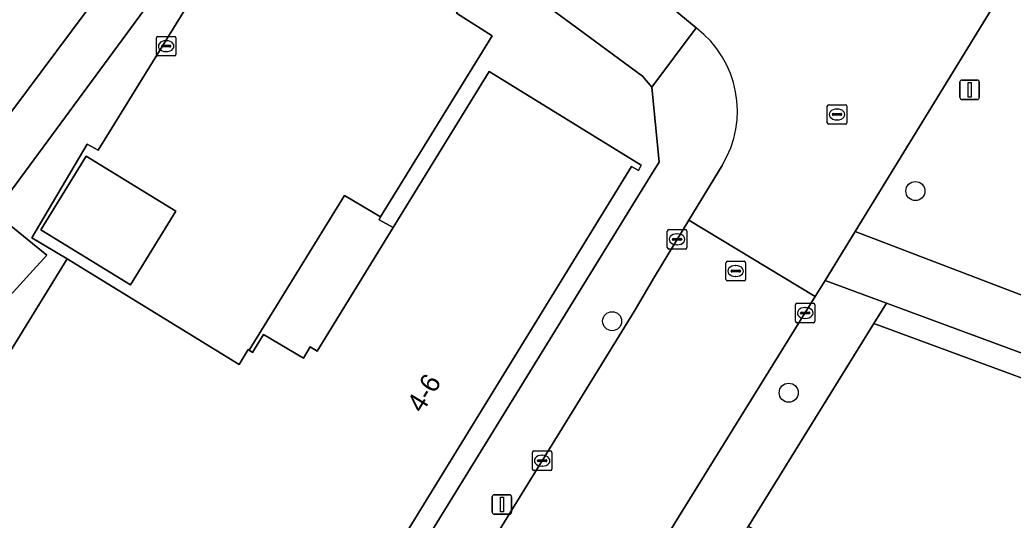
# Model space of a CAD drawing. Extents: x 162803 to 163818, y 381639 to 382475.
# Drawn here: x 163036.2 to 163087.2, y 381869.7 to 381895.4 of the extents above; entities that cross this region are included whole.
import ezdxf

# ---------------------------------------------------------------- set-up
doc = ezdxf.new("R2010")
doc.units = 0
for name, color, linetype in [('IMGEO_Boom', 7, 'Continuous'), ('IMGEO_Erf', 7, 'Continuous'), ('IMGEO_Groenvoorziening', 7, 'Continuous'), ('IMGEO_Hek', 7, 'Continuous'), ('IMGEO_Kolk', 7, 'Continuous'), ('IMGEO_Lichtmast', 7, 'Continuous'), ('IMGEO_Open_loods', 7, 'Continuous'), ('IMGEO_Pand', 7, 'Continuous'), ('IMGEO_Pand_nummerreeks', 7, 'Continuous'), ('IMGEO_Parkeervlak_open', 7, 'Continuous'), ('IMGEO_Rijbaan_lokaal_open', 7, 'Continuous'), ('IMGEO_Rioolput', 7, 'Continuous'), ('IMGEO_Voetpad_gesloten', 7, 'Continuous'), ('IMGEO_Voetpad_halfverhard', 7, 'Continuous'), ('IMGEO_Voetpad_open', 7, 'Continuous')]:
    doc.layers.add(name, color=color, linetype=linetype)

msp = doc.modelspace()

# ---------------------------------------------------------------- linework, layer by layer
at = {"layer": 'IMGEO_Boom'}
for centre in [(163082.188, 381886.567), (163066.621, 381879.881), (163075.685, 381876.209)]:
    msp.add_circle(centre, 0.489, dxfattribs=at)
at = {"layer": 'IMGEO_Erf'}
msp.add_lwpolyline([(163038.651, 381883.086), (163036.828, 381884.162), (163039.676, 381888.972), (163040.229, 381888.673), (163050.041, 381904.572), (163054.928, 381901.596), (163055.361, 381902.269), (163050.243, 381906.292), (163034.914, 381885.439), (163037.605, 381883.275), (163019.349, 381863.218), (163031.785, 381852.208), (163033.858, 381855.537), (163033.587, 381855.698), (163033.798, 381856.014), (163025.478, 381861.115), (163025.295, 381860.793), (163025.018, 381860.951)], close=True, dxfattribs=at)
msp.add_lwpolyline([(163023.213, 381895.682), (163025.63, 381893.703), (163027.222, 381895.579), (163029.852, 381893.348), (163030.812, 381894.576), (163035.802, 381890.676), (163039.628, 381895.786)], dxfattribs=at)
at = {"layer": 'IMGEO_Groenvoorziening'}
for points in [[(163114.975, 381943.024), (163089.592, 381901.666), (163087.523, 381898.23), (163086.13, 381895.957), (163079.099, 381884.487), (163082.234, 381883.288), (163093.032, 381879.159), (163093.046, 381879.154), (163099.204, 381891.124), (163115.517, 381885.092), (163117.64, 381890.509), (163137.039, 381941.324)], [(163080.701, 381880.807), (163080.058, 381879.766), (163094.718, 381874.361), (163106.979, 381869.84), (163107.395, 381869.476), (163107.586, 381869.167), (163107.691, 381868.676), (163107.588, 381868.15), (163106.369, 381864.493), (163105.791, 381862.206), (163105.668, 381861.359), (163105.323, 381858.982), (163102.085, 381839.303), (163103.298, 381839.057), (163105.724, 381853.567), (163106.512, 381858.816)], [(163106.871, 381871.137), (163080.701, 381880.807)], [(163102.801, 381836.083), (163103.298, 381839.057), (163102.085, 381839.303), (163105.323, 381858.982), (163105.668, 381861.359), (163103.938, 381861.555), (163101.326, 381862.698), (163100.347, 381864.983), (163100.592, 381866.37), (163099.245, 381865.84), (163096.919, 381865.881), (163094.553, 381867.962), (163093.941, 381870.94), (163094.718, 381874.361), (163080.058, 381879.766), (163073.629, 381869.358), (163092.744, 381857.74), (163097.666, 381854.748), (163098.212, 381854.416), (163076.88, 381813.818)]]:
    msp.add_lwpolyline(points, dxfattribs=at)
for points in [[(163068.653, 381891.896), (163068.177, 381892.47), (163060.268, 381898.298), (163058.635, 381895.702), (163060.471, 381894.547), (163054.736, 381885.241), (163054.657, 381885.087), (163055.376, 381884.686), (163060.306, 381892.706), (163068.12, 381887.891), (163067.971, 381887.615), (163067.621, 381887.819), (163052.073, 381862.544), (163052.426, 381862.343), (163052.243, 381862.047), (163052.762, 381861.77), (163052.897, 381861.856), (163068.715, 381887.535), (163069.028, 381888.05)], [(163080.058, 381879.766), (163080.701, 381880.807), (163077.556, 381881.969), (163077.052, 381881.146), (163070.17, 381870.045), (163067.916, 381866.384), (163066.543, 381864.226), (163069.38, 381862.489), (163071.602, 381866.077), (163073.629, 381869.358)]]:
    msp.add_lwpolyline(points, close=True, dxfattribs=at)
at = {"layer": 'IMGEO_Hek'}
msp.add_lwpolyline([(163050.243, 381906.292), (163034.914, 381885.439), (163037.605, 381883.275), (163019.349, 381863.218)], dxfattribs=at)
at = {"layer": 'IMGEO_Kolk'}
for p, q in [((163043.226, 381893.583), (163043.226, 381894.435)), ((163043.301, 381894.509), (163044.153, 381894.509)), ((163043.714, 381894.289), (163043.739, 381894.289)), ((163044.227, 381894.435), (163044.227, 381893.583)), ((163043.485, 381894.003), (163043.485, 381894.015)), ((163043.923, 381893.966), (163043.525, 381893.966)), ((163043.528, 381894.052), (163043.926, 381894.052)), ((163043.737, 381893.729), (163043.712, 381893.729)), ((163043.969, 381894.015), (163043.969, 381894.003)), ((163044.153, 381893.509), (163043.301, 381893.509)), ((163069.454, 381883.66), (163069.454, 381884.512)), ((163069.529, 381884.586), (163070.381, 381884.586)), ((163070.455, 381884.512), (163070.455, 381883.66)), ((163069.713, 381884.08), (163069.713, 381884.092)), ((163070.151, 381884.043), (163069.753, 381884.043)), ((163069.756, 381884.129), (163070.154, 381884.129)), ((163069.942, 381884.366), (163069.967, 381884.366)), ((163070.197, 381884.092), (163070.197, 381884.08)), ((163070.381, 381883.586), (163069.529, 381883.586)), ((163069.965, 381883.806), (163069.94, 381883.806)), ((163076.032, 381879.876), (163076.032, 381880.728)), ((163076.107, 381880.802), (163076.959, 381880.802)), ((163076.52, 381880.582), (163076.545, 381880.582)), ((163077.033, 381880.728), (163077.033, 381879.876)), ((163076.291, 381880.296), (163076.291, 381880.308)), ((163076.729, 381880.259), (163076.331, 381880.259)), ((163076.334, 381880.345), (163076.732, 381880.345)), ((163076.543, 381880.022), (163076.518, 381880.022)), ((163076.775, 381880.308), (163076.775, 381880.296)), ((163076.959, 381879.802), (163076.107, 381879.802)), ((163062.604, 381873.215), (163063.456, 381873.215)), ((163062.529, 381872.289), (163062.529, 381873.141)), ((163062.788, 381872.709), (163062.788, 381872.721)), ((163062.831, 381872.758), (163063.229, 381872.758)), ((163063.017, 381872.995), (163063.042, 381872.995)), ((163063.272, 381872.721), (163063.272, 381872.709)), ((163063.53, 381873.141), (163063.53, 381872.289)), ((163063.456, 381872.215), (163062.604, 381872.215)), ((163063.226, 381872.672), (163062.828, 381872.672)), ((163063.04, 381872.435), (163063.015, 381872.435))]:
    msp.add_line(p, q, dxfattribs=at)
for points in [[(163043.226, 381893.583), (163043.226, 381894.435)], [(163043.301, 381894.509), (163044.153, 381894.509)], [(163044.227, 381894.435), (163044.227, 381893.583)], [(163044.153, 381893.509), (163043.301, 381893.509)], [(163069.454, 381883.66), (163069.454, 381884.512)], [(163069.529, 381884.586), (163070.381, 381884.586)], [(163070.455, 381884.512), (163070.455, 381883.66)], [(163070.381, 381883.586), (163069.529, 381883.586)], [(163076.032, 381879.876), (163076.032, 381880.728)], [(163076.107, 381880.802), (163076.959, 381880.802)], [(163077.033, 381880.728), (163077.033, 381879.876)], [(163076.959, 381879.802), (163076.107, 381879.802)], [(163062.604, 381873.215), (163063.456, 381873.215)], [(163062.529, 381872.289), (163062.529, 381873.141)], [(163063.53, 381873.141), (163063.53, 381872.289)], [(163063.456, 381872.215), (163062.604, 381872.215)]]:
    msp.add_lwpolyline(points, dxfattribs=at)
for centre, radius, start, end in [((163043.303, 381894.433), 0.0765, 91.552, 178.448), ((163043.303, 381894.433), 0.0765, 91.552, 178.448), ((163044.151, 381894.433), 0.0765, 1.552, 88.448), ((163044.151, 381894.433), 0.0765, 1.552, 88.448), ((163043.525, 381894.012), 0.0403, 85.8775, 175.7526), ((163043.522, 381894.002), 0.0366, 178.938, 274.7102), ((163043.926, 381894.009), 0.043, 264.8664, 352.4533), ((163043.93, 381894.014), 0.0386, 1.7309, 96.639), ((163043.303, 381893.585), 0.0765, 181.552, 268.448), ((163043.303, 381893.585), 0.0765, 181.552, 268.448), ((163044.151, 381893.585), 0.0765, 271.552, 358.448), ((163044.151, 381893.585), 0.0765, 271.552, 358.448), ((163069.531, 381884.51), 0.0765, 91.552, 178.448), ((163069.531, 381884.51), 0.0765, 91.552, 178.448), ((163070.379, 381884.51), 0.0765, 1.552, 88.448), ((163070.379, 381884.51), 0.0765, 1.552, 88.448), ((163069.753, 381884.089), 0.0403, 85.8775, 175.7526), ((163069.75, 381884.079), 0.0366, 178.938, 274.7102), ((163070.154, 381884.086), 0.043, 264.8664, 352.4533), ((163070.158, 381884.091), 0.0386, 1.7309, 96.639), ((163069.531, 381883.662), 0.0765, 181.552, 268.448), ((163069.531, 381883.662), 0.0765, 181.552, 268.448), ((163070.379, 381883.662), 0.0765, 271.552, 358.448), ((163070.379, 381883.662), 0.0765, 271.552, 358.448), ((163076.109, 381880.726), 0.0765, 91.552, 178.448), ((163076.109, 381880.726), 0.0765, 91.552, 178.448), ((163076.957, 381880.726), 0.0765, 1.552, 88.448), ((163076.957, 381880.726), 0.0765, 1.552, 88.448), ((163076.109, 381879.878), 0.0765, 181.552, 268.448), ((163076.109, 381879.878), 0.0765, 181.552, 268.448), ((163076.331, 381880.305), 0.0403, 85.8775, 175.7526), ((163076.328, 381880.295), 0.0366, 178.938, 274.7102), ((163076.732, 381880.302), 0.043, 264.8664, 352.4533), ((163076.736, 381880.307), 0.0386, 1.7309, 96.639), ((163076.957, 381879.878), 0.0765, 271.552, 358.448), ((163076.957, 381879.878), 0.0765, 271.552, 358.448), ((163062.606, 381873.139), 0.0765, 91.552, 178.448), ((163062.606, 381873.139), 0.0765, 91.552, 178.448), ((163063.454, 381873.139), 0.0765, 1.552, 88.448), ((163063.454, 381873.139), 0.0765, 1.552, 88.448), ((163062.828, 381872.718), 0.0403, 85.8775, 175.7526), ((163062.825, 381872.708), 0.0366, 178.938, 274.7102), ((163063.229, 381872.715), 0.043, 264.8664, 352.4533), ((163063.233, 381872.72), 0.0386, 1.7309, 96.639), ((163062.606, 381872.291), 0.0765, 181.552, 268.448), ((163062.606, 381872.291), 0.0765, 181.552, 268.448), ((163063.454, 381872.291), 0.0765, 271.552, 358.448), ((163063.454, 381872.291), 0.0765, 271.552, 358.448)]:
    msp.add_arc(centre, radius, start, end, dxfattribs=at)
for centre, major_axis, ratio, start_param, end_param in [((163043.713, 381894.009), (-0.387, 0.002), 0.722429, 4.712389, 7.853982), ((163043.738, 381894.009), (-0.39, 0.002), 0.717154, 1.570796, 4.712389), ((163069.941, 381884.086), (-0.387, 0.002), 0.722429, 4.712389, 7.853982), ((163069.966, 381884.086), (-0.39, 0.002), 0.717154, 1.570796, 4.712389), ((163076.519, 381880.302), (-0.387, 0.002), 0.722429, 4.712389, 7.853982), ((163076.544, 381880.302), (-0.39, 0.002), 0.717154, 1.570796, 4.712389), ((163063.016, 381872.715), (-0.387, 0.002), 0.722429, 4.712389, 7.853982), ((163063.041, 381872.715), (-0.39, 0.002), 0.717154, 1.570796, 4.712389)]:
    msp.add_ellipse(centre, major_axis=major_axis, ratio=ratio, start_param=start_param, end_param=end_param, dxfattribs=at)
at = {"layer": 'IMGEO_Lichtmast'}
for p, q in [((163084.476, 381891.369), (163084.476, 381892.169)), ((163084.476, 381892.169), (163084.476, 381891.369)), ((163084.576, 381892.269), (163085.366, 381892.269)), ((163085.366, 381892.269), (163084.576, 381892.269)), ((163085.466, 381892.169), (163085.466, 381891.369)), ((163085.466, 381891.369), (163085.466, 381892.169)), ((163085.366, 381891.269), (163084.576, 381891.269)), ((163084.576, 381891.269), (163085.366, 381891.269)), ((163060.467, 381870.066), (163060.467, 381870.866)), ((163060.467, 381870.866), (163060.467, 381870.066)), ((163060.567, 381870.966), (163061.357, 381870.966)), ((163061.357, 381870.966), (163060.567, 381870.966)), ((163061.457, 381870.866), (163061.457, 381870.066)), ((163061.457, 381870.066), (163061.457, 381870.866)), ((163061.357, 381869.966), (163060.567, 381869.966)), ((163060.567, 381869.966), (163061.357, 381869.966))]:
    msp.add_line(p, q, dxfattribs=at)
for points in [[(163084.896, 381892.144), (163085.046, 381892.144), (163085.046, 381891.394), (163084.896, 381891.394), (163084.896, 381892.144)], [(163060.887, 381870.841), (163061.037, 381870.841), (163061.037, 381870.091), (163060.887, 381870.091), (163060.887, 381870.841)]]:
    msp.add_lwpolyline(points, dxfattribs=at)
for centre, start, end in [((163084.576, 381892.169), 90, 180), ((163084.576, 381892.169), 90, 180), ((163085.366, 381892.169), 0, 90), ((163085.366, 381892.169), 360, 90), ((163084.576, 381891.369), 180, 270), ((163084.576, 381891.369), 180, 270), ((163085.366, 381891.369), 270, 0), ((163085.366, 381891.369), 270, 0), ((163060.567, 381870.866), 90, 180), ((163060.567, 381870.866), 90, 180), ((163061.357, 381870.866), 0, 90), ((163061.357, 381870.866), 360, 90), ((163060.567, 381870.066), 180, 270), ((163060.567, 381870.066), 180, 270), ((163061.357, 381870.066), 270, 0), ((163061.357, 381870.066), 270, 0)]:
    msp.add_arc(centre, 0.1, start, end, dxfattribs=at)
at = {"layer": 'IMGEO_Open_loods'}
msp.add_lwpolyline([(163044.218, 381885.539), (163039.624, 381888.364), (163037.291, 381884.581), (163041.895, 381881.752)], close=True, dxfattribs=at)
at = {"layer": 'IMGEO_Pand'}
msp.add_lwpolyline([(163052.073, 381862.544), (163067.621, 381887.819), (163067.971, 381887.615), (163068.12, 381887.891), (163060.306, 381892.706), (163055.376, 381884.686), (163051.48, 381878.348), (163051.127, 381878.561), (163050.773, 381877.977), (163048.727, 381879.199), (163048.162, 381878.277), (163047.993, 381878.397), (163047.942, 381878.433), (163047.476, 381877.66), (163038.651, 381883.086), (163025.018, 381860.951)], dxfattribs=at)
at = {"layer": 'IMGEO_Parkeervlak_open'}
for points in [[(163054.928, 381901.596), (163050.041, 381904.572), (163040.229, 381888.673), (163039.676, 381888.972), (163036.828, 381884.162), (163038.651, 381883.086), (163047.476, 381877.66), (163047.942, 381878.433), (163047.993, 381878.397), (163052.886, 381886.336), (163054.736, 381885.241), (163060.471, 381894.547), (163058.635, 381895.702), (163060.268, 381898.298)], [(163041.895, 381881.752), (163037.291, 381884.581), (163039.624, 381888.364), (163044.218, 381885.539)]]:
    msp.add_lwpolyline(points, close=True, dxfattribs=at)
at = {"layer": 'IMGEO_Rijbaan_lokaal_open'}
for points in [[(163072.265, 381887.886), (163070.551, 381885.066), (163077.052, 381881.146), (163077.556, 381881.969), (163079.099, 381884.487), (163086.13, 381895.957), (163087.523, 381898.23), (163081.136, 381902.235), (163079.504, 381899.647)], [(163072.605, 381898.25), (163071.739, 381898.909), (163069.543, 381896.09), (163070.942, 381894.943)]]:
    msp.add_lwpolyline(points, dxfattribs=at)
msp.add_lwpolyline([(163066.543, 381864.226), (163067.916, 381866.384), (163070.17, 381870.045), (163077.052, 381881.146), (163070.551, 381885.066), (163068.789, 381882.168), (163067.744, 381880.386), (163057.663, 381863.991), (163055.048, 381859.753), (163051.115, 381853.378), (163048.348, 381848.843), (163045.94, 381844.899), (163052.231, 381840.99), (163057.473, 381849.543), (163062.554, 381857.831), (163064.731, 381861.322)], close=True, dxfattribs=at)
msp.add_arc((163067.7, 381890.683), 5.353, 328.5049, 52.7314, dxfattribs=at)
at = {"layer": 'IMGEO_Rioolput'}
for p, q in [((163077.666, 381890.074), (163077.666, 381890.926)), ((163077.741, 381891), (163078.593, 381891)), ((163078.154, 381890.78), (163078.179, 381890.78)), ((163078.667, 381890.926), (163078.667, 381890.074)), ((163077.925, 381890.494), (163077.925, 381890.506)), ((163078.363, 381890.457), (163077.965, 381890.457)), ((163077.968, 381890.543), (163078.366, 381890.543)), ((163078.177, 381890.22), (163078.152, 381890.22)), ((163078.409, 381890.506), (163078.409, 381890.494)), ((163078.593, 381890), (163077.741, 381890)), ((163072.541, 381882.957), (163073.393, 381882.957)), ((163072.466, 381882.031), (163072.466, 381882.883)), ((163072.725, 381882.451), (163072.725, 381882.463)), ((163073.163, 381882.414), (163072.765, 381882.414)), ((163072.768, 381882.5), (163073.166, 381882.5)), ((163072.954, 381882.737), (163072.979, 381882.737)), ((163073.209, 381882.463), (163073.209, 381882.451)), ((163073.467, 381882.883), (163073.467, 381882.031)), ((163073.393, 381881.957), (163072.541, 381881.957)), ((163072.977, 381882.177), (163072.952, 381882.177))]:
    msp.add_line(p, q, dxfattribs=at)
for points in [[(163077.666, 381890.074), (163077.666, 381890.926)], [(163077.741, 381891), (163078.593, 381891)], [(163078.667, 381890.926), (163078.667, 381890.074)], [(163078.593, 381890), (163077.741, 381890)], [(163072.541, 381882.957), (163073.393, 381882.957)], [(163072.466, 381882.031), (163072.466, 381882.883)], [(163073.467, 381882.883), (163073.467, 381882.031)], [(163073.393, 381881.957), (163072.541, 381881.957)]]:
    msp.add_lwpolyline(points, dxfattribs=at)
for centre, radius, start, end in [((163077.743, 381890.924), 0.0765, 91.552, 178.448), ((163077.743, 381890.924), 0.0765, 91.552, 178.448), ((163078.591, 381890.924), 0.0765, 1.552, 88.448), ((163078.591, 381890.924), 0.0765, 1.552, 88.448), ((163077.743, 381890.076), 0.0765, 181.552, 268.448), ((163077.743, 381890.076), 0.0765, 181.552, 268.448), ((163077.965, 381890.503), 0.0403, 85.8775, 175.7526), ((163077.962, 381890.493), 0.0366, 178.938, 274.7102), ((163078.366, 381890.5), 0.043, 264.8664, 352.4533), ((163078.37, 381890.505), 0.0386, 1.7309, 96.639), ((163078.591, 381890.076), 0.0765, 271.552, 358.448), ((163078.591, 381890.076), 0.0765, 271.552, 358.448), ((163072.543, 381882.881), 0.0765, 91.552, 178.448), ((163072.543, 381882.881), 0.0765, 91.552, 178.448), ((163073.391, 381882.881), 0.0765, 1.552, 88.448), ((163073.391, 381882.881), 0.0765, 1.552, 88.448), ((163072.765, 381882.46), 0.0403, 85.8775, 175.7526), ((163072.762, 381882.45), 0.0366, 178.938, 274.7102), ((163073.166, 381882.457), 0.043, 264.8664, 352.4533), ((163073.17, 381882.462), 0.0386, 1.7309, 96.639), ((163072.543, 381882.033), 0.0765, 181.552, 268.448), ((163072.543, 381882.033), 0.0765, 181.552, 268.448), ((163073.391, 381882.033), 0.0765, 271.552, 358.448), ((163073.391, 381882.033), 0.0765, 271.552, 358.448)]:
    msp.add_arc(centre, radius, start, end, dxfattribs=at)
for centre, major_axis, ratio, start_param, end_param in [((163078.153, 381890.5), (-0.387, 0.002), 0.722429, 4.712389, 7.853982), ((163078.178, 381890.5), (-0.39, 0.002), 0.717154, 1.570796, 4.712389), ((163072.953, 381882.457), (-0.387, 0.002), 0.722429, 4.712389, 7.853982), ((163072.978, 381882.457), (-0.39, 0.002), 0.717154, 1.570796, 4.712389)]:
    msp.add_ellipse(centre, major_axis=major_axis, ratio=ratio, start_param=start_param, end_param=end_param, dxfattribs=at)
at = {"layer": 'IMGEO_Voetpad_gesloten'}
msp.add_lwpolyline([(163054.657, 381885.087), (163054.736, 381885.241), (163052.886, 381886.336), (163047.993, 381878.397), (163048.162, 381878.277), (163048.727, 381879.199), (163050.773, 381877.977), (163051.127, 381878.561), (163051.48, 381878.348), (163055.376, 381884.686)], close=True, dxfattribs=at)
msp.add_lwpolyline([(163108.123, 381873.628), (163093.046, 381879.154), (163093.032, 381879.159), (163082.234, 381883.288), (163079.099, 381884.487), (163077.556, 381881.969), (163080.701, 381880.807), (163106.871, 381871.137)], dxfattribs=at)
at = {"layer": 'IMGEO_Voetpad_halfverhard'}
for points in [[(163014.646, 381900.893), (163025.843, 381891.535), (163030.492, 381887.595), (163033.443, 381885.093), (163035.497, 381883.351), (163027.8, 381874.781), (163025.912, 381872.628), (163024.418, 381870.921), (163021.124, 381867.159), (163018.388, 381864.069), (163019.349, 381863.218), (163037.605, 381883.275), (163034.914, 381885.439), (163050.243, 381906.292)], [(163039.628, 381895.786), (163035.802, 381890.676), (163034.629, 381889.294), (163033.037, 381887.418), (163028.335, 381891.407), (163025.63, 381893.703), (163023.213, 381895.682)]]:
    msp.add_lwpolyline(points, dxfattribs=at)
at = {"layer": 'IMGEO_Voetpad_open'}
for points in [[(162926.547, 382003.598), (162928.941, 382001.641), (162955.144, 381981.044), (162956.756, 381979.777), (162998.706, 381946.802), (162999.395, 381946.261), (163001.097, 381944.923), (163048.763, 381907.455), (163050.243, 381906.292), (163055.361, 381902.269), (163054.928, 381901.596), (163060.268, 381898.298), (163068.177, 381892.47), (163068.653, 381891.896), (163070.942, 381894.943), (163069.543, 381896.09), (163067.173, 381897.988), (163058.977, 381904.423), (163054.221, 381908.123)], [(163070.942, 381894.943), (163068.653, 381891.896), (163069.028, 381888.05), (163068.715, 381887.535), (163052.897, 381861.856), (163052.762, 381861.77), (163052.152, 381860.804), (163046.085, 381850.982), (163046.176, 381850.915), (163041.909, 381843.762)], [(163067.744, 381880.386), (163068.789, 381882.168), (163070.551, 381885.066), (163072.265, 381887.886)], [(163045.11, 381843.538), (163045.94, 381844.899), (163048.348, 381848.843), (163051.115, 381853.378), (163055.048, 381859.753), (163057.663, 381863.991), (163067.744, 381880.386)]]:
    msp.add_lwpolyline(points, dxfattribs=at)
msp.add_arc((163067.7, 381890.683), 5.353, 328.5049, 52.7314, dxfattribs=at)

# ---------------------------------------------------------------- texts
at = {"layer": 'IMGEO_Pand_nummerreeks'}
msp.add_text('4-6', height=1, rotation=58.4059, dxfattribs=at).set_placement((163056.872, 381875.116))

doc.saveas('drawing.dxf')
